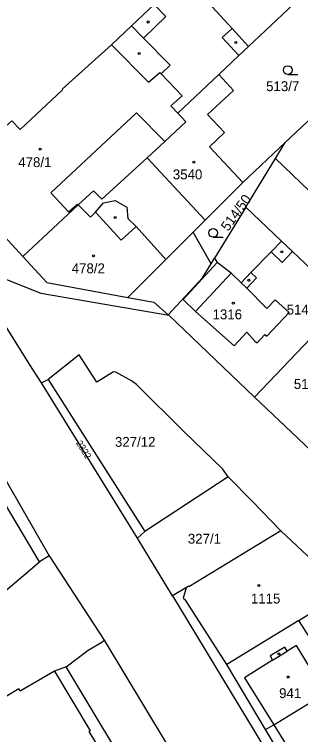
# Model space of a CAD drawing. Extents: x -679220 to -673243, y -1075091 to -1066557.
# Drawn here: x -676017.5 to -675968.3, y -1072146.6 to -1072022.8 of the extents above; entities that cross this region are included whole.
import ezdxf

# ---------------------------------------------------------------- set-up
doc = ezdxf.new("R2010")
doc.units = 0
for name, color, linetype in [('Hranice parcel', 7, 'Continuous'), ('Parcelní čísla', 7, 'Continuous'), ('Vnitřní kresba', 7, 'Continuous'), ('Značky budov', 7, 'Continuous'), ('Značky kultur', 7, 'Continuous')]:
    doc.layers.add(name, color=color, linetype=linetype)

msp = doc.modelspace()

# ---------------------------------------------------------------- linework, layer by layer
at = {"layer": 'Hranice parcel'}
for p, q in [((-675977.27, -1072028.34), (-675968.52, -1072020.07)), ((-675970.95, -1072044.83), (-675962.48, -1072036.83)), ((-675978.22, -1072051.69), (-675970.95, -1072044.83)), ((-675972.62, -1072047.57), (-675970.95, -1072044.83)), ((-675984.7, -1072058.17), (-675994.69, -1072047.49)), ((-675977.73, -1072055.95), (-675972.62, -1072047.57)), ((-675972.62, -1072047.57), (-675962.16, -1072057.72)), ((-676028.71, -1072050.67), (-676016.02, -1072064.44)), ((-675978.22, -1072051.69), (-675984.7, -1072058.17)), ((-675977.73, -1072055.95), (-675983.1, -1072064.73)), ((-675960.63, -1072072.21), (-675969.69, -1072063.6)), ((-675983.69, -1072065.7), (-675983.1, -1072064.73)), ((-675983.1, -1072064.73), (-675982.65, -1072065.47)), ((-675976.24, -1072088.58), (-675960.63, -1072072.21)), ((-675990.95, -1072074.52), (-675991.06, -1072074.43)), ((-675990.95, -1072074.52), (-675976.24, -1072088.58)), ((-676012.81, -1072086.13), (-676011.66, -1072085.56)), ((-675996.34, -1072112.83), (-676012.81, -1072086.13)), ((-676011.66, -1072085.56), (-675995.07, -1072111.67)), ((-675980.75, -1072102.28), (-675995.07, -1072111.67)), ((-675995.07, -1072111.67), (-675996.34, -1072112.83)), ((-675960.5, -1072122.13), (-675971.7, -1072111.57)), ((-676011.5, -1072115.85), (-676013.15, -1072116.89)), ((-676011.5, -1072115.85), (-676002.04, -1072130.35)), ((-675987.89, -1072121.27), (-675990.34, -1072122.74)), ((-675968.63, -1072126.95), (-675981, -1072134.52)), ((-675974.36, -1072145.69), (-675981, -1072134.52)), ((-675965.35, -1072160.63), (-675974.36, -1072145.69))]:
    msp.add_line(p, q, dxfattribs=at)
for points in [[(-675988.29, -1072016.27), (-675993.45, -1072021.14), (-675997.34, -1072024.81), (-676000.8, -1072028.07), (-676009.28, -1072035.69), (-676009.2, -1072035.78), (-676016.47, -1072042.6), (-676017.87, -1072041.11), (-676028.71, -1072050.67)], [(-675977.27, -1072028.34), (-675980.08, -1072025.26), (-675988.29, -1072016.27)], [(-675982.38, -1072033.19), (-675978.94, -1072029.92), (-675977.27, -1072028.34)], [(-675994.69, -1072047.49), (-675991.62, -1072044.68), (-675988, -1072041.3), (-675989.41, -1072039.83), (-675982.38, -1072033.19)], [(-675982.38, -1072033.19), (-675979.84, -1072035.92), (-675984.28, -1072040.03), (-675981.36, -1072043.15), (-675983.96, -1072045.61), (-675978.22, -1072051.69)], [(-676016.02, -1072064.44), (-676006.49, -1072055.57), (-676003.87, -1072053.13), (-676002.47, -1072054.58), (-675994.69, -1072047.49)], [(-676051.66, -1072055.61), (-676041.29, -1072068.57), (-676020.94, -1072099.46), (-676011.5, -1072115.85)], [(-675969.69, -1072063.6), (-675971.61, -1072061.77), (-675977.73, -1072055.95)], [(-675983.69, -1072065.7), (-675986.79, -1072060.26), (-675984.7, -1072058.17)], [(-675974.09, -1072073.37), (-675977.53, -1072069.86), (-675975.88, -1072068.1), (-675976.86, -1072067.17), (-675973.38, -1072063.63), (-675971.46, -1072065.45), (-675969.69, -1072063.6)], [(-676016.02, -1072064.44), (-676011.89, -1072068.92), (-675997.99, -1072071.46), (-675993.52, -1072072.25), (-675991.06, -1072074.43)], [(-676012.81, -1072086.13), (-676014.27, -1072083.86), (-676025.75, -1072065.64)], [(-676025.75, -1072065.64), (-676012.93, -1072070.74), (-675990.95, -1072074.52)], [(-675991.06, -1072074.43), (-675985.15, -1072068.09), (-675983.69, -1072065.7)], [(-675982.65, -1072065.47), (-675988.51, -1072071.84), (-675986.34, -1072073.87)], [(-675976.16, -1072078.95), (-675975.8, -1072079.29), (-675974.46, -1072077.82), (-675974.14, -1072078.11), (-675970.3, -1072074.06), (-675972.69, -1072071.89), (-675974.09, -1072073.37)], [(-675986.34, -1072073.87), (-675979.73, -1072079.79), (-675977.55, -1072077.41), (-675976.16, -1072078.95)], [(-675980.75, -1072102.28), (-675981.74, -1072100.91), (-675988.33, -1072094.53), (-675996.49, -1072086.45), (-675997.38, -1072085.79), (-676000.07, -1072084.3), (-676000.45, -1072084.27), (-676003.29, -1072086.04), (-676006.33, -1072081.35), (-676011.66, -1072085.56)], [(-675976.24, -1072088.58), (-675969.9, -1072094.63), (-675958.48, -1072105.46)], [(-676013.15, -1072116.89), (-676019.98, -1072105.48), (-676022.66, -1072100.85)], [(-675971.7, -1072111.57), (-675976.56, -1072106.53), (-675980.75, -1072102.28)], [(-675971.7, -1072111.57), (-675987.53, -1072121.19), (-675987.59, -1072121.09), (-675987.89, -1072121.27)], [(-675990.34, -1072122.74), (-675996.15, -1072113.13), (-675996.34, -1072112.83)], [(-676027.08, -1072128.72), (-676026.9, -1072128.59), (-676026.97, -1072128.51), (-676024.74, -1072126.76), (-676013.15, -1072116.89)], [(-675981, -1072134.52), (-675988.13, -1072123.34), (-675988.23, -1072123.4), (-675988.41, -1072123.1), (-675987.89, -1072121.27)], [(-675968.63, -1072126.95), (-675967.23, -1072126.09), (-675960.5, -1072122.13)], [(-675990.34, -1072122.74), (-675965.06, -1072164.5), (-675944.22, -1072198.66), (-675920.45, -1072238.88), (-675899.68, -1072273.04), (-675879.13, -1072306.74), (-675849.47, -1072355.79), (-675790.19, -1072454.14)], [(-675965.46, -1072128.98), (-675966.81, -1072129.82), (-675968.63, -1072126.95)], [(-676008.59, -1072134.94), (-676004.81, -1072132.06), (-676002.47, -1072130.7), (-676002.04, -1072130.35)], [(-676002.04, -1072130.35), (-675984.64, -1072159.26), (-675978.83, -1072168.99), (-675961.64, -1072197.66)], [(-676008.59, -1072134.94), (-676010.58, -1072135.65), (-676016.49, -1072139.09), (-676016.72, -1072138.71), (-676032.8, -1072148.4), (-676032.57, -1072148.78), (-676038.37, -1072152.3), (-676046.51, -1072160.26)], [(-675961.64, -1072197.66), (-675968.73, -1072201.32), (-676008.59, -1072134.94)], [(-675974.36, -1072145.69), (-675972.91, -1072144.92), (-675964.04, -1072139.48), (-675962.74, -1072138.64), (-675960.4, -1072137.25), (-675957.83, -1072135.67)]]:
    msp.add_lwpolyline(points, dxfattribs=at)
at = {"layer": 'Vnitřní kresba'}
for p, q in [((-675993.45, -1072021.14), (-675991.45, -1072023.19)), ((-675991.45, -1072023.19), (-675995.28, -1072026.93)), ((-675997.34, -1072024.81), (-675995.28, -1072026.93)), ((-675981.78, -1072026.81), (-675980.08, -1072025.26)), ((-675995.28, -1072026.93), (-675990.74, -1072031.58)), ((-675978.94, -1072029.92), (-675981.78, -1072026.81)), ((-676000.8, -1072028.07), (-675994.44, -1072034.49)), ((-675990.74, -1072031.58), (-675992.25, -1072033.03)), ((-675994.44, -1072034.49), (-675992.47, -1072032.81)), ((-675992.47, -1072032.81), (-675992.25, -1072033.03)), ((-675992.25, -1072033.03), (-675988.63, -1072036.82)), ((-675988.63, -1072036.82), (-675990.62, -1072038.56)), ((-675990.62, -1072038.56), (-675989.41, -1072039.83)), ((-676011.19, -1072053.51), (-675996.5, -1072039.72)), ((-675996.5, -1072039.72), (-675991.62, -1072044.68)), ((-676011.19, -1072053.51), (-676008.15, -1072056.75)), ((-676008.15, -1072056.75), (-676006.64, -1072055.42)), ((-676006.64, -1072055.42), (-676006.49, -1072055.57)), ((-676003.54, -1072056.79), (-676002.15, -1072055.21)), ((-676002.15, -1072055.21), (-676000.17, -1072054.83)), ((-676000.17, -1072054.83), (-675998.17, -1072055.93)), ((-676006.49, -1072055.57), (-676004.42, -1072057.66)), ((-675998.17, -1072055.93), (-675997.98, -1072057.92)), ((-676004.42, -1072057.66), (-676003.54, -1072056.79)), ((-676003.54, -1072056.79), (-675999.14, -1072061.62)), ((-675997.98, -1072057.92), (-675996.57, -1072059.29)), ((-675999.14, -1072061.62), (-675996.57, -1072059.29)), ((-675991.46, -1072064.93), (-675996.57, -1072059.29)), ((-675991.46, -1072064.93), (-675986.79, -1072060.26)), ((-675973.38, -1072063.63), (-675971.61, -1072061.77)), ((-675991.46, -1072064.93), (-675997.99, -1072071.46)), ((-675980.27, -1072067.3), (-675982.65, -1072065.47)), ((-675986.34, -1072073.87), (-675980.27, -1072067.3)), ((-675978.52, -1072068.94), (-675980.27, -1072067.3)), ((-675978.52, -1072068.94), (-675976.86, -1072067.17)), ((-675977.53, -1072069.86), (-675978.52, -1072068.94)), ((-675971.04, -1072131.54), (-675973.55, -1072133.04)), ((-675970.62, -1072132.22), (-675971.04, -1072131.54)), ((-675969.05, -1072131.24), (-675970.62, -1072132.22)), ((-675964.04, -1072139.48), (-675969.05, -1072131.24)), ((-675973.55, -1072133.04), (-675973.16, -1072133.81)), ((-675973.16, -1072133.81), (-675970.62, -1072132.22)), ((-675973.16, -1072133.81), (-675977.95, -1072136.79)), ((-676010.58, -1072135.65), (-676004.44, -1072145.91)), ((-675977.95, -1072136.79), (-675972.91, -1072144.92)), ((-675972.91, -1072144.92), (-675967.05, -1072154.38)), ((-676004.44, -1072145.91), (-676004.65, -1072146.04)), ((-676004.65, -1072146.04), (-675995.68, -1072160.94))]:
    msp.add_line(p, q, dxfattribs=at)
at = {"layer": 'Značky budov'}
for centre in [(-675994.51, -1072024.14), (-675979.45, -1072027.66), (-675996.03, -1072029.57), (-676013.05, -1072046), (-675986.65, -1072048.23), (-676000.14, -1072057.72), (-675971.56, -1072063.64), (-676003.87, -1072064.31), (-675977.19, -1072068.52), (-675979.87, -1072072.45), (-675975.49, -1072120.95), (-675972.07, -1072132.68), (-675970.47, -1072136.68)]:
    msp.add_circle(centre, 0.175, dxfattribs=at)
at = {"layer": 'Značky kultur'}
for p, q in [((-675970.53, -1072033.15), (-675968.78, -1072033.15)), ((-675983.34, -1072061.13), (-675981.59, -1072061.13))]:
    msp.add_line(p, q, dxfattribs=at)
for centre in [(-675970.53, -1072032.4), (-675983.34, -1072060.38)]:
    msp.add_circle(centre, 0.75, dxfattribs=at)

# ---------------------------------------------------------------- texts
at = {"layer": 'Parcelní čísla'}
for s, p in [('513/7', (-675974.24, -1072036.02)), ('478/1', (-676016.79, -1072049.07)), ('3540', (-675990.25, -1072051.18)), ('478/2', (-676007.61, -1072067.31)), ('514/58', (-675970.71, -1072074.4)), ('1316', (-675983.43, -1072075.23)), ('514/59', (-675969.48, -1072087.19)), ('327/12', (-676000.19, -1072097.13)), ('327/1', (-675987.68, -1072113.77)), ('1115', (-675976.85, -1072124.05)), ('941', (-675972.01, -1072140.3))]:
    msp.add_text(s, height=1.7, dxfattribs=at).set_placement(p)
for s, height, rotation, p in [('514/50', 1.7, 54, (-675980.77, -1072060.2)), ('2322', 1.14, 302, (-676006.92, -1072096.48))]:
    msp.add_text(s, height=height, rotation=rotation, dxfattribs=at).set_placement(p)

doc.saveas('drawing.dxf')
